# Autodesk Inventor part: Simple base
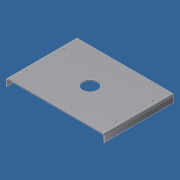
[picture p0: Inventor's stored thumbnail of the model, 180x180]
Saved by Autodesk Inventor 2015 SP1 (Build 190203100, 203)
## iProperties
Category: Mechanical Engineering Drawing and Design - CADD
Manager: Fábio Ricardo de Oliveira Souza
Company: SENAI - Serviço Nacional de Aprendizagem Industrial
Created: 2011-06
Part Number: Simple base
Material: Steel
Description: Stainless Steel (DIN- X6CrNiTi18-10)
Document SubType Name: Sheet Metal
Designer: Guilherme Augusto Franco de Souza
Engineer: George Geraldo de Oliveia Silva
Authority: Fábio Ricardo de Oliveira Soza
Density: 7.85 g/cm^3
Sheet Metal Rule: Default_mm
Flat Pattern Width: 27.4572 cm
Flat Pattern Length: 32.5 cm
Flat Pattern Area: 892.358 cm^2
Sheet Metal Width: 274,572 mm
Sheet Metal Length: 325,000 mm
Sheet Metal Area: 89235,796 mm^2
Appearance: Stainless - Brushed
Subject: WorldSkill 2011 - London, England
Author: Guilherme Augusto Franco de Souza
Revision Number: 00
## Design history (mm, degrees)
node "Face1"
  sketch "Sketch1"
    geometry: L1 (-162.5, 117.5)-(162.5, 117.5); L2 (162.5, 117.5)-(162.5, -117.5); L3 (162.5, -117.5)-(-162.5, -117.5); L4 (-162.5, -117.5)-(-162.5, 117.5); 3 further points
    constraints: 8 end point, 2 midpoint, 2 parallel, 1 horizontal, 1 horizontal alignment, 1 perpendicular, 1 vertical alignment
    dimensions: "d0" = 325 distance of L1.start L1.end; "d1" = 235 distance of L3.end L1.start
sketch "Sketch2"
  geometry: L1 (162.5, 117.5)-(162.5, -117.5) reference; L2 (-162.5, 117.5)-(162.5, 117.5) reference; L3 (-162.5, -117.5)-(-162.5, 117.5) reference; 5 further points
  constraints: 2 horizontal alignment, 2 vertical alignment
  dimensions: "d3" = 12.5 distance from line of L3 point (-150, 62.5); "d4" = 12.5 distance from line of L1 point (150, 62.5); "d5" = 55 distance from line of L2 point (-150, 62.5); "d6" = 125 distance of point (-150, -62.5) point (-150, 62.5)
hole "Hole1" sketch "Sketch2" at (-150, 62.5), (-150, -62.5), (150, 62.5), (150, -62.5) diameter "d7" = 7; stored, may be unused: countersink angle "d11" = 90 deg, drill point angle "d13" = 118 deg; dims "d8" = 6, "d9" = 4, "d10" = 2, "d12" = 3 (= Thickness)
node "Flange1"
sketch "Sketch4"
  geometry: 1 further point
hole "Hole2" sketch "Sketch4" at (0, 0) diameter "d24" = 50; stored, may be unused: countersink angle "d28" = 90 deg, drill point angle "d30" = 118 deg; dims "d25" = 6, "d26" = 4, "d27" = 2, "d29" = 3 (= Thickness)
body "Solid1"
face "Plate1" dims "Thickness" = 3 (derived)
sketch "Sketch3"
  geometry: L1 through (162.5, 0) direction (-1, 0); L2 through (0, -12.5) direction (0, -1); L3 (0, -25)-(325, -25); L4 (325, -25)-(325, 0)
  constraints: 6 end point, 1 horizontal, 1 perpendicular, 1 vertical
face "Plate2" dims "d14" = 3 (= BendReliefWidth), "d15" = 1.5 (= BendReliefDepth), "d16" = 6 (= MinimumRemnant), "d17" = 3 (= BendRadius), "d18" = 25, "d19" = 90 deg, "d20" = 3 (= BendRadius), "d21" = 12 (= CornerReliefSize), "d22" = 3 (= GapSize), "d23" = 3 (= JacobiRadiusSize), "SeamGap" = 0.01, "Thickness" = 3 (derived)
bend "Bend1" dims "d14" = 3 (= BendReliefWidth), "d15" = 1.5 (= BendReliefDepth), "d16" = 6 (= MinimumRemnant), "d17" = 3 (= BendRadius), "d18" = 25, "d19" = 90 deg, "d20" = 3 (= BendRadius), "SeamGap" = 0.01, "Thickness" = 3 (derived)
feature "Corner1" dims "d18" = 25, "d19" = 90 deg, "d21" = 12 (= CornerReliefSize), "d22" = 3 (= GapSize), "d23" = 3 (= JacobiRadiusSize)
feature "Definition1"
other parameters: "BendRadius" = 3 (= Thickness), "BendReliefWidth" = 3 (= Thickness), "BendReliefDepth" = 1.5 (= 0.5 x Thickness), "CornerReliefSize" = 12 (= 4 x Thickness), "MinimumRemnant" = 6 (= 2 x Thickness), "TransitionRadius" = 3 (= BendRadius), "JacobiRadiusSize" = 3 (= BendRadius), "GapSize" = 3 (= Thickness), "d2" = 3 (= BendRadius), "BendRadius" = 3, "BendReliefDepth" = 1.5, "BendReliefWidth" = 3, "CornerReliefSize" = 12, "GapSize" = 3, "JacobiRadiusSize" = 3, "MinimumRemnant" = 6, "Thickness" = 3, "TransitionRadius" = 3
